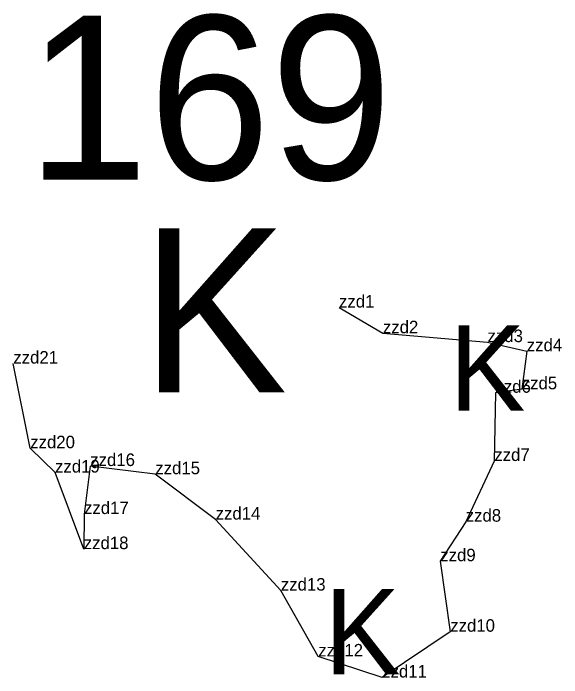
# Model space of a CAD drawing. Extents: x 2072529 to 2268796, y 436423 to 470406.
# Drawn here: x 2189397.6 to 2189616.3, y 453333.4 to 453598.3 of the extents above; entities that cross this region are included whole.
import ezdxf

# ---------------------------------------------------------------- set-up
doc = ezdxf.new("R2010")
doc.units = 0
for name, color, linetype in [('Default', 7, 'Continuous'), ('Exist Environmental Wetland Boundary', 7, 'Continuous'), ('Exist Environmental Wetland Boundary Cogo Comment', 7, 'Continuous'), ('Exist Hydro Swamp or Marsh', 7, 'Continuous'), ('Old_Level_20', 7, 'Continuous')]:
    doc.layers.add(name, color=color, linetype=linetype)

msp = doc.modelspace()

# ---------------------------------------------------------------- linework, layer by layer
at = {"layer": 'Exist Environmental Wetland Boundary'}
msp.add_lwpolyline([(2189527.48, 453480.95), (2189544.98, 453470.71), (2189586.7, 453467.17), (2189602.36, 453463.53), (2189600.35, 453448.36), (2189589.86, 453447), (2189589.4, 453419.78), (2189578, 453395.59), (2189567.86, 453379.81), (2189571.83, 453351.72), (2189544.68, 453333.46), (2189519.21, 453341.85), (2189504.28, 453368.12), (2189478.28, 453396.41), (2189454.22, 453414.51), (2189428.26, 453417.78), (2189425.79, 453398.63), (2189425.69, 453384.65), (2189414.24, 453415.16), (2189404.34, 453424.86), (2189397.59, 453458.62)], dxfattribs=at)
at = {"layer": 'Old_Level_20'}
for p, q in [((2189527.48, 453480.95), (2189527.48, 453480.95)), ((2189544.98, 453470.71), (2189544.98, 453470.71)), ((2189586.7, 453467.17), (2189586.7, 453467.17)), ((2189602.36, 453463.53), (2189602.36, 453463.53)), ((2189397.59, 453458.62), (2189397.59, 453458.62)), ((2189589.86, 453447), (2189589.86, 453447)), ((2189600.35, 453448.36), (2189600.35, 453448.36)), ((2189404.34, 453424.86), (2189404.34, 453424.86)), ((2189589.4, 453419.78), (2189589.4, 453419.78)), ((2189428.26, 453417.78), (2189428.26, 453417.78)), ((2189414.24, 453415.16), (2189414.24, 453415.16)), ((2189454.22, 453414.51), (2189454.22, 453414.51)), ((2189425.79, 453398.63), (2189425.79, 453398.63)), ((2189478.28, 453396.41), (2189478.28, 453396.41)), ((2189578, 453395.59), (2189578, 453395.59)), ((2189425.69, 453384.65), (2189425.69, 453384.65)), ((2189567.86, 453379.81), (2189567.86, 453379.81)), ((2189504.28, 453368.12), (2189504.28, 453368.12)), ((2189571.83, 453351.72), (2189571.83, 453351.72)), ((2189519.21, 453341.85), (2189519.21, 453341.85)), ((2189544.68, 453333.46), (2189544.68, 453333.46))]:
    msp.add_line(p, q, dxfattribs=at)

# ---------------------------------------------------------------- texts
at = {"layer": 'Default'}
for s, p in [('169', (2189402.89, 453531.95)), ('169', (2189402.89, 453531.95)), ('K', (2189448.55, 453447.18))]:
    msp.add_text(s, height=65.34, dxfattribs=at).set_placement(p)
at = {"layer": 'Exist Environmental Wetland Boundary Cogo Comment'}
for s, p in [('zzd1', (2189527.48, 453480.95)), ('zzd2', (2189544.98, 453470.71)), ('zzd3', (2189586.7, 453467.17)), ('zzd4', (2189602.36, 453463.53)), ('zzd21', (2189397.59, 453458.62)), ('zzd6', (2189589.86, 453447)), ('zzd5', (2189600.35, 453448.36)), ('zzd20', (2189404.34, 453424.86)), ('zzd7', (2189589.4, 453419.78)), ('zzd16', (2189428.26, 453417.78)), ('zzd19', (2189414.24, 453415.16)), ('zzd15', (2189454.22, 453414.51)), ('zzd17', (2189425.79, 453398.63)), ('zzd14', (2189478.28, 453396.41)), ('zzd8', (2189578, 453395.59)), ('zzd18', (2189425.69, 453384.65)), ('zzd9', (2189567.86, 453379.81)), ('zzd13', (2189504.28, 453368.12)), ('zzd10', (2189571.83, 453351.72)), ('zzd12', (2189519.21, 453341.85)), ('zzd11', (2189544.68, 453333.46))]:
    msp.add_text(s, height=5, dxfattribs=at).set_placement(p)
at = {"layer": 'Exist Hydro Swamp or Marsh'}
for p in [(2189571.46, 453439.86), (2189521.62, 453334.79)]:
    msp.add_text('K', height=34, dxfattribs=at).set_placement(p)

doc.saveas('drawing.dxf')
